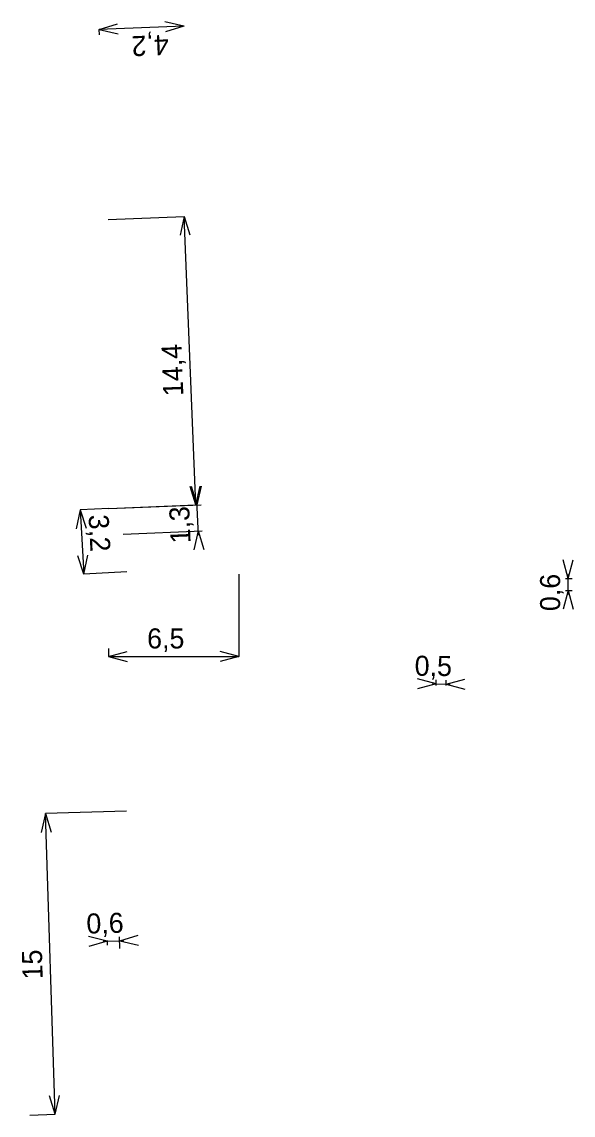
# Model space of a CAD drawing. Extents: x -744070.2 to -744042.7, y -1044491.2 to -1044436.7.
import ezdxf

# ---------------------------------------------------------------- set-up
doc = ezdxf.new("R2010")
doc.units = 0
doc.layers.add('Kota_NN', color=7, linetype='Continuous')
doc.layers.add('Kota_VN', color=7, linetype='Continuous')

msp = doc.modelspace()

# ---------------------------------------------------------------- linework, layer by layer
at = {"layer": 'Kota_NN'}
for p, q in [((-744067.294, -1044461.038), (-744067.492, -1044461.978)), ((-744065.87, -1044460.96), (-744067.294, -1044461.038)), ((-744067.294, -1044461.038), (-744067.119, -1044464.234)), ((-744067.294, -1044461.038), (-744066.996, -1044461.951)), ((-744067.119, -1044464.234), (-744067.417, -1044463.321)), ((-744067.119, -1044464.234), (-744066.921, -1044463.294)), ((-744042.957, -1044464.457), (-744043.207, -1044463.53)), ((-744042.957, -1044464.457), (-744042.71, -1044463.528)), ((-744064.974, -1044464.117), (-744067.119, -1044464.234)), ((-744059.374, -1044464.234), (-744059.379, -1044468.35)), ((-744042.955, -1044465.251), (-744042.958, -1044464.257)), ((-744043.088, -1044464.457), (-744042.757, -1044464.457)), ((-744042.956, -1044465.051), (-744043.203, -1044465.98)), ((-744043.086, -1044465.052), (-744042.756, -1044465.051)), ((-744042.956, -1044465.051), (-744042.706, -1044465.978)), ((-744065.879, -1044467.944), (-744065.88, -1044468.342)), ((-744065.88, -1044468.342), (-744064.952, -1044468.095)), ((-744059.379, -1044468.35), (-744060.307, -1044468.1)), ((-744065.88, -1044468.342), (-744059.379, -1044468.35)), ((-744065.88, -1044468.342), (-744064.952, -1044468.592)), ((-744059.379, -1044468.35), (-744060.307, -1044468.597)), ((-744049.542, -1044469.718), (-744050.472, -1044469.957)), ((-744049.542, -1044469.718), (-744050.468, -1044469.46)), ((-744049.742, -1044469.716), (-744048.84, -1044469.724)), ((-744049.543, -1044469.793), (-744049.54, -1044469.518)), ((-744049.041, -1044469.798), (-744049.038, -1044469.522)), ((-744049.04, -1044469.722), (-744048.11, -1044469.483)), ((-744049.04, -1044469.722), (-744048.114, -1044469.98)), ((-744069.022, -1044476.188), (-744069.242, -1044477.123)), ((-744064.99, -1044476.061), (-744069.022, -1044476.188)), ((-744068.549, -1044491.191), (-744069.022, -1044476.188)), ((-744069.022, -1044476.188), (-744068.745, -1044477.108)), ((-744068.549, -1044491.191), (-744068.826, -1044490.271)), ((-744068.549, -1044491.191), (-744068.329, -1044490.256)), ((-744069.808, -1044491.231), (-744068.549, -1044491.191))]:
    msp.add_line(p, q, dxfattribs=at)
at = {"layer": 'Kota_VN'}
for p, q in [((-744066.347, -1044437.069), (-744065.43, -1044436.783)), ((-744062.128, -1044436.894), (-744066.347, -1044437.069)), ((-744066.336, -1044437.327), (-744066.347, -1044437.069)), ((-744066.347, -1044437.069), (-744065.409, -1044437.279)), ((-744062.128, -1044436.894), (-744063.066, -1044436.684)), ((-744062.128, -1044436.894), (-744063.045, -1044437.18)), ((-744062.129, -1044436.884), (-744062.128, -1044436.894)), ((-744065.903, -1044446.546), (-744062.103, -1044446.394)), ((-744062.103, -1044446.394), (-744062.315, -1044447.331)), ((-744061.527, -1044460.786), (-744062.103, -1044446.394)), ((-744062.103, -1044446.394), (-744061.818, -1044447.311)), ((-744061.527, -1044460.786), (-744061.812, -1044459.869)), ((-744061.461, -1044460.784), (-744061.746, -1044459.867)), ((-744061.527, -1044460.786), (-744061.315, -1044459.849)), ((-744061.461, -1044460.784), (-744061.249, -1044459.847)), ((-744061.401, -1044462.286), (-744061.469, -1044460.584)), ((-744065.87, -1044460.96), (-744061.261, -1044460.776)), ((-744065.87, -1044460.96), (-744061.527, -1044460.786)), ((-744065.157, -1044462.236), (-744061.209, -1044462.078)), ((-744061.409, -1044462.086), (-744061.621, -1044463.023)), ((-744061.409, -1044462.086), (-744061.124, -1044463.003)), ((-744065.95, -1044482.549), (-744066.884, -1044482.325)), ((-744065.311, -1044482.914), (-744065.327, -1044482.332)), ((-744065.321, -1044482.532), (-744064.4, -1044482.259)), ((-744065.95, -1044482.549), (-744066.871, -1044482.822)), ((-744066.15, -1044482.555), (-744065.121, -1044482.527)), ((-744065.951, -1044482.518), (-744065.945, -1044482.749)), ((-744065.321, -1044482.532), (-744064.387, -1044482.756))]:
    msp.add_line(p, q, dxfattribs=at)

# ---------------------------------------------------------------- texts
at = {"layer": 'Kota_NN'}
for s, rotation, p in [('3,2', 273.1321, (-744066.88, -1044461.289)), ('0,6', 90.1242, (-744043.354, -1044466.082)), ('6,5', 359.9248, (-744063.956, -1044467.944)), ('0,5', 359.4575, (-744050.614, -1044469.307)), ('15', 91.8036, (-744069.162, -1044484.446))]:
    msp.add_text(s, height=1, rotation=rotation, dxfattribs=at).set_placement(p)
at = {"layer": 'Kota_VN'}
for s, rotation, p in [('4,2', 182.3704, (-744062.895, -1044437.326)), ('14,4', 92.2923, (-744062.145, -1044455.341)), ('1,3', 92.2921, (-744061.785, -1044462.69)), ('0,6', 1.5622, (-744066.973, -1044482.177))]:
    msp.add_text(s, height=1, rotation=rotation, dxfattribs=at).set_placement(p)

doc.saveas('drawing.dxf')
